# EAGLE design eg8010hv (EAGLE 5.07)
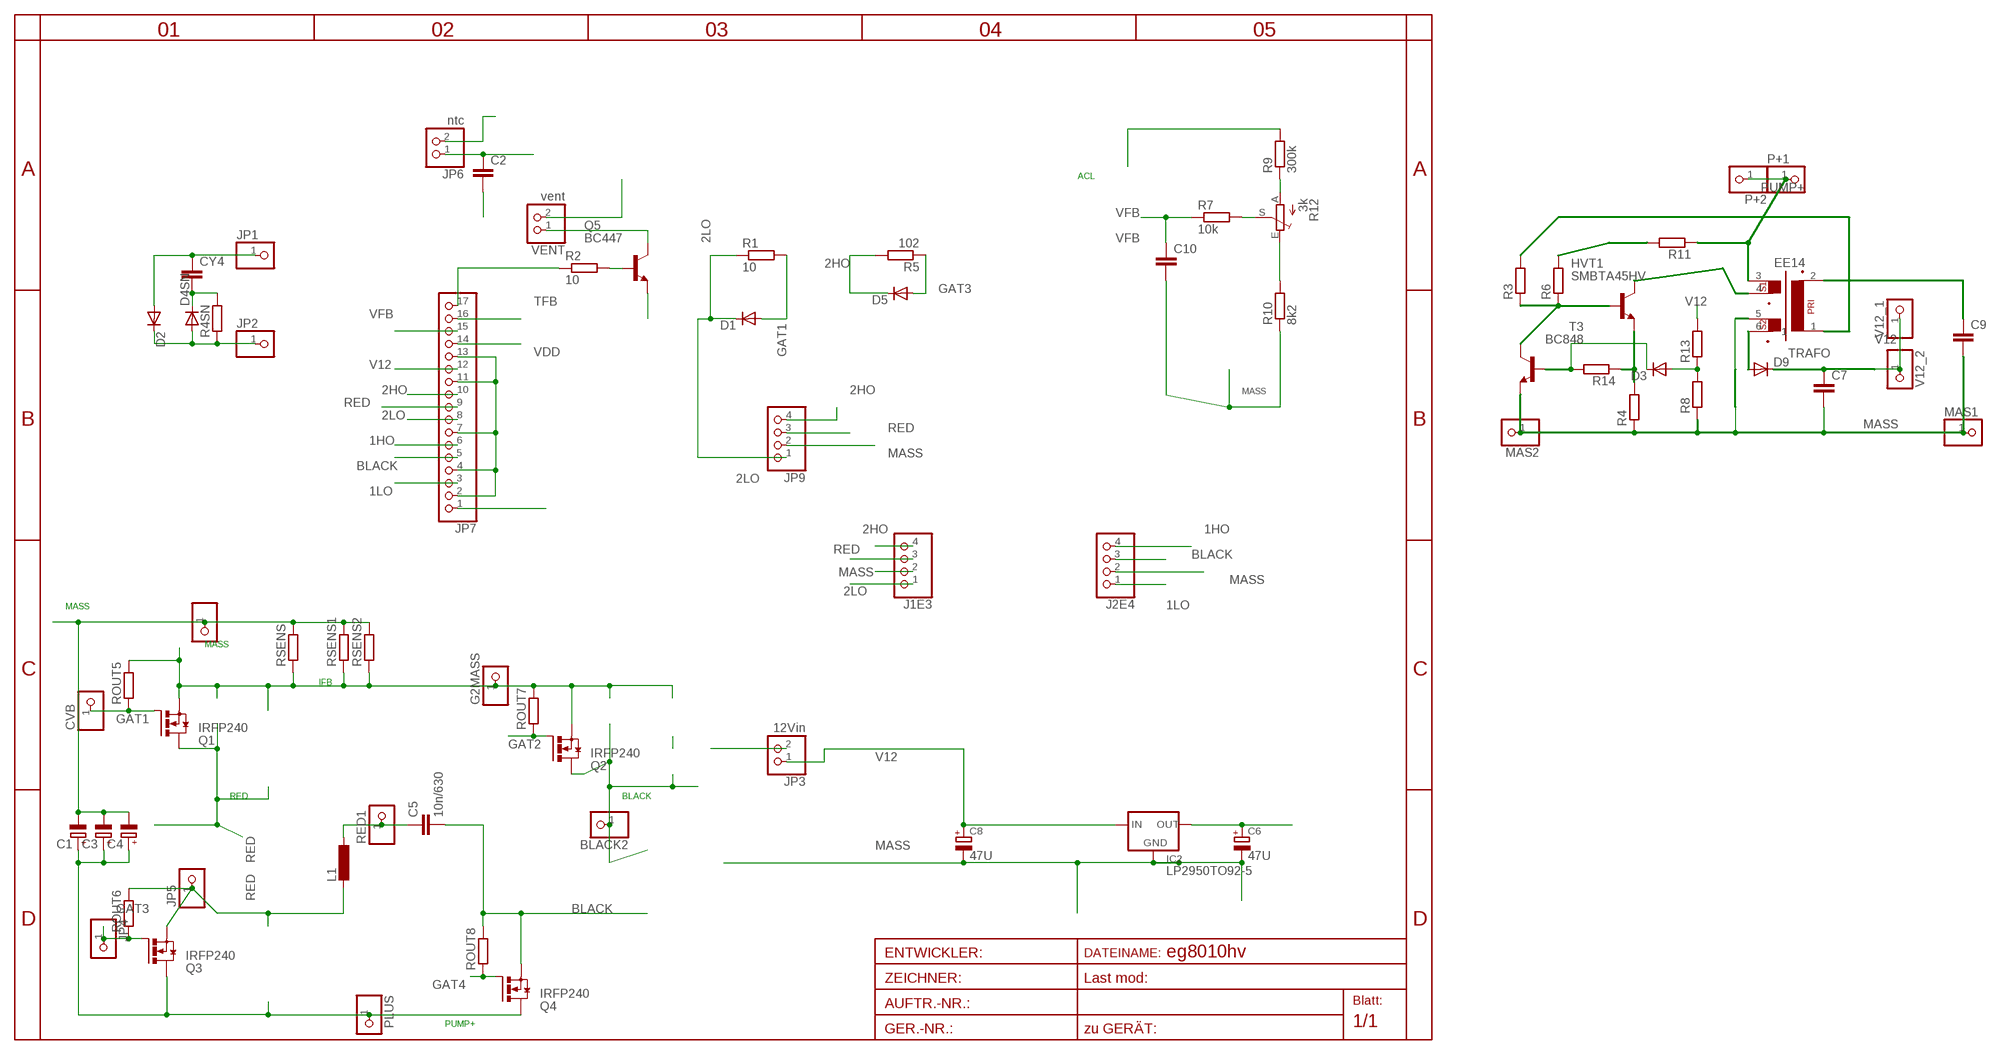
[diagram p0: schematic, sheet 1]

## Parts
BLACK2  PINHD-1X12MM3  [1X2MM3]
C1  CPOL-EUE5-13  [E5-13]
C2  C-EUC1206  [C1206]
C3  CPOL-EUE5-13  [E5-13]
C4  CPOL-EUE5-13  [E5-13]
C5  10n/630  C-EU275-173X316  [C275-173X316]
C6  47U  CPOL-EUE2.5-6  [E2,5-6]
C7  C-EUC1206  [C1206]
C8  47U  CPOL-EUE2.5-6  [E2,5-6]
C9  C-EUC0805  [C0805]
C10  C-EUC0805  [C0805]
CVB  PINHD-1X11MM0  [1X1MM0]
CY4  CXXC10B5  [XC10B5]
D1  DIODE-MINIMELF  [MINIMELF]
D2  DIODE-SMC  [SMC]
D3  DIODE-MINIMELF  [MINIMELF]
D4SN  DIODE-P1-10  [P1-10]
D5  DIODE-MINIMELF  [MINIMELF]
D9  DIODE-SMA-DO214  [SMA-DO214AC]
G2MASS  PINHD-1X11MM0  [1X1MM0]
HVT1  SMBTA45HV  [SOT23HV]
IC2  LP2950TO92-5  [T092-5]
J1E3  PINHD-1X4  [1X04]
J2E4  PINHD-1X4  [1X04]
JP1  PINHD-1X11MM0  [1X1MM0]
JP2  PINHD-1X11MM0  [1X1MM0]
JP3  12Vin  PINHD-1X2STR  [1X02]
JP4  PINHD-1X11MM0  [1X1MM0]
JP5  PINHD-1X11MM0  [1X1MM0]
JP6  ntc  PINHD-1X2STR  [1X02]
JP7  PINHD-1X17  [1X17]
JP9  PINHD-1X4  [1X04]
L1  L-EU4.13  [0204/13]
MAS1  PINHD-1X11X0.4  [1X01]
MAS2  PINHD-1X11X0.4  [1X01]
MINUS  PINHD-1X12MM3  [1X2MM3]
P+1  PINHD-1X11X0.4  [1X01]
P+2  PINHD-1X11X0.4  [1X01]
PLUS  PINHD-1X12MM3  [1X2MM3]
Q1  IRFP240  [TO247BV]
Q2  IRFP240  [TO247BV]
Q3  IRFP240  [TO247BV]
Q4  IRFP240  [TO247BV]
Q5  BC447  [TO92-EBC]
R1  10  R-EU_R0805  [R0805]
R2  10  R-EU_R0805  [R0805]
R3  R-EU_R0805  [R0805]
R4  R-EU_R0805  [R0805]
R4SN  R-EU_0207/10  [0207/10]
R5  102  R-EU_R1206  [R1206]
R6  R-EU_R1206  [R1206]
R7  10k  R-EU_R0805  [R0805]
R8  R-EU_R0805  [R0805]
R9  300k  R-EU_0207/20  [0207/20]
R10  8k2  R-EU_R0805  [R0805]
R11  R-EU_R1206  [R1206]
R12  3k  TRIM_EU-CA6V  [CA6V]
R13  R-EU_R0805  [R0805]
R14  R-EU_R0805  [R0805]
RED1  PINHD-1X12MM3  [1X2MM3]
ROUT5  R-EU_0207/10  [0207/10]
ROUT6  R-EU_0207/10  [0207/10]
ROUT7  R-EU_0207/10  [0207/10]
ROUT8  R-EU_0207/10  [0207/10]
RSENS  R-EU_0204/7  [0204/7]
RSENS1  R-EU_0204/7  [0204/7]
RSENS2  R-EU_0922V  [0922V]
T3  BC848  [SOT23]
TRAFO  EE14  [EE14]
V12_1  PINHD-1X11X0.4  [1X01]
V12_2  PINHD-1X11X0.4  [1X01]
VENT  vent  PINHD-1X2STR  [1X02]

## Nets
1HO: J2E4.4 JP7.6
1LO: J2E4.1 JP7.3
2HO: D5.C J1E3.4 JP7.10 JP9.4 R5.2
2LO: D1.C J1E3.1 JP7.8 JP9.1 R1.1
A: D9.A TRAFO.6
ACL: C5.1 L1.1 R9.2 RED1.1
B1C2: HVT1.1(B) R3.1 R6.1 T3.C
BLACK: BLACK2.1 C5.2 J2E4.3 JP7.5 Q2.D Q4.S ROUT8.2
BT1: D3.C R14.2 T3.B
C1: HVT1.3(C) TRAFO.4
DRAIN: D2.C D4SN.A JP2.1 R4SN.1
EB: HVT1.2(E) R4.2 R14.1
GAT1: CVB.1 D1.A Q1.G R1.2 ROUT5.1
GAT2: Q2.G ROUT7.1
GAT3: D5.A JP4.1 Q3.G R5.1 ROUT6.1
GAT4: Q4.G ROUT8.1
IFB: G2MASS.1 JP7.1 Q1.S Q2.S ROUT5.2 ROUT7.2 RSENS1.1 RSENS2.1 RSENS.1
MASS: C1.- C2.2 C3.- C4.- C6.- C7.2 C8.- C9.2 C10.2 IC2.2(GND) J1E3.2 J2E4.2 JP3.2 JP7.2 JP7.4 JP7.7 JP7.11 JP7.13 JP9.2 MAS1.1 MAS2.1 MINUS.1 Q5.E R4.1 R8.1 R10.1 RSENS1.2 RSENS2.2 RSENS.2 T3.E TRAFO.5
N$1: Q5.C VENT.1
N$2: Q5.B R2.2
N$3: JP7.17 R2.1
N$6: R3.2 TRAFO.1
N$7: C9.1 TRAFO.2
N$8: R6.2 R11.2
N$10: D3.A R8.2 R13.1
N$29: R10.2 R12.E
N$30: R9.1 R12.A
N$31: R7.2 R12.S
PUMP+: C1.+ C3.+ C4.+ P+1.1 P+2.1 PLUS.1 Q3.D Q4.D R11.1 TRAFO.3
RED: J1E3.3 JP5.1 JP7.9 JP9.3 L1.2 Q1.D Q3.S ROUT6.2
SNUB2: CY4.2 D4SN.C R4SN.2
SOURCE: CY4.1 D2.A JP1.1
TFB: C2.1 JP6.1 JP7.16
V12: C7.1 C8.+ D9.K(C) IC2.3(IN) JP3.1 JP7.12 R13.2 V12_1.1 V12_2.1
VDD: C6.+ IC2.1(OUT) JP6.2 JP7.14 VENT.2
VFB: C10.1 JP7.15 R7.1

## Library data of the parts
BLACK2 CVB G2MASS JP1 JP2 JP4 JP5 MAS1 MAS2 MINUS P+1 P+2 PLUS RED1 V12_1 V12_2 = pinhead:PINHD-1X1: PIN HEADER
C1 C3 C4 = rcl:CPOL-EU: POLARIZED CAPACITOR, European symbol
C2 C5 C7 C9 C10 = rcl:C-EU: CAPACITOR, European symbol
C6 C8 = rcl-2:CPOL-EU: POLARIZED CAPACITOR, European symbol
CY4 = rcl:CX: X CAPACITOR
D1-D3 D4SN D5 D9 = diode:DIODE-: DIODE
HVT1 = transistor-npn:SMBTA45
IC2 = v-reg:LP2950?*: Source: http://cache.national.com/ds/LP/LP2950.pdf
J1E3 J2E4 JP9 = pinhead:PINHD-1X4: PIN HEADER
JP3 JP6 VENT = pinhead:PINHD-1X2: PIN HEADER
JP7 = pinhead:PINHD-1X17: PIN HEADER
L1 = rcl:L-EU: INDUCTOR, European symbol
Q1-Q4 = transistor-power:IRFP240: HEXFET Power MosFet Source: http://www.irf.com/
Q5 = transistor-npn:BC447*: NPN Transistor
R1-R4 R4SN R5 R6 R8 R11 R13 R14 ROUT5-ROUT8 RSENS RSENS1 RSENS2 = rcl:R-EU_: RESISTOR, European symbol
R7 R9 R10 = rcl-2:R-EU_: RESISTOR, European symbol
R12 = pot:TRIM_EU-: POTENTIOMETER
T3 = transistor:BC848: NPN TRANSISTOR
TRAFO = trafo:EE14

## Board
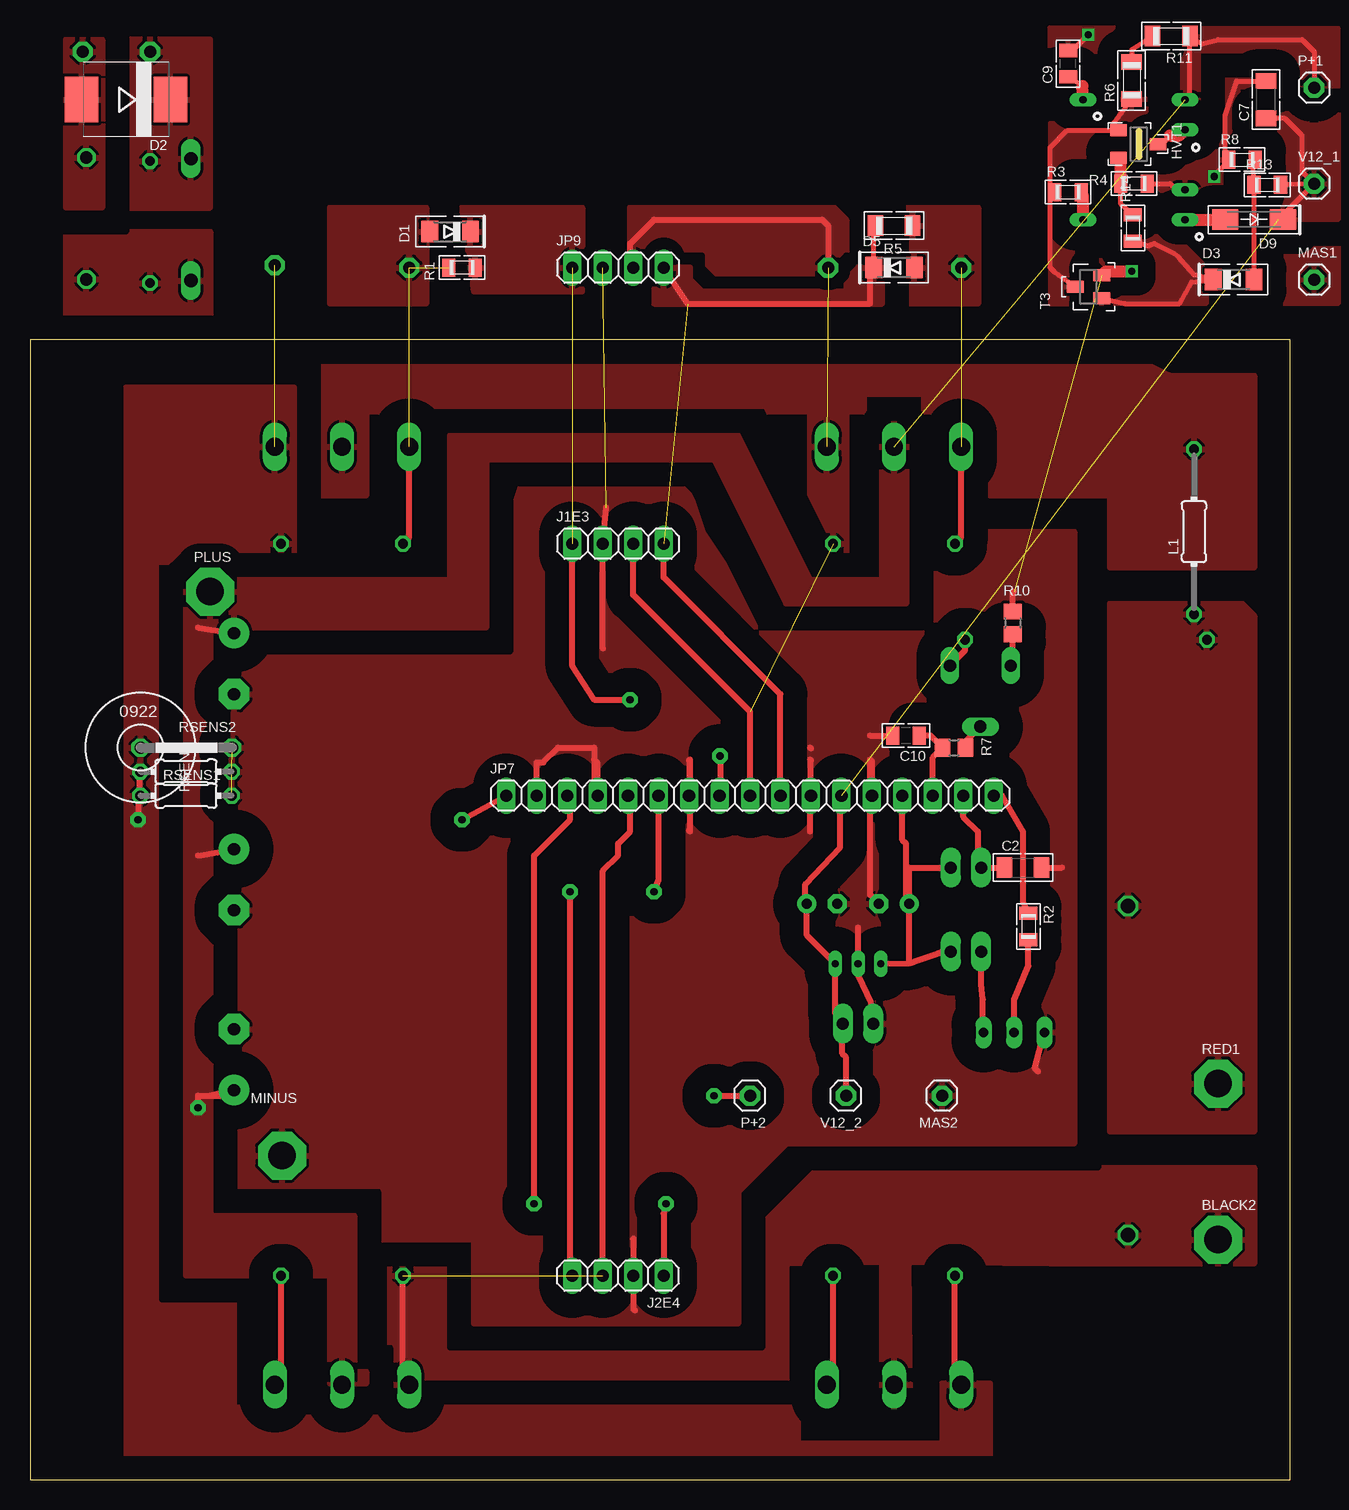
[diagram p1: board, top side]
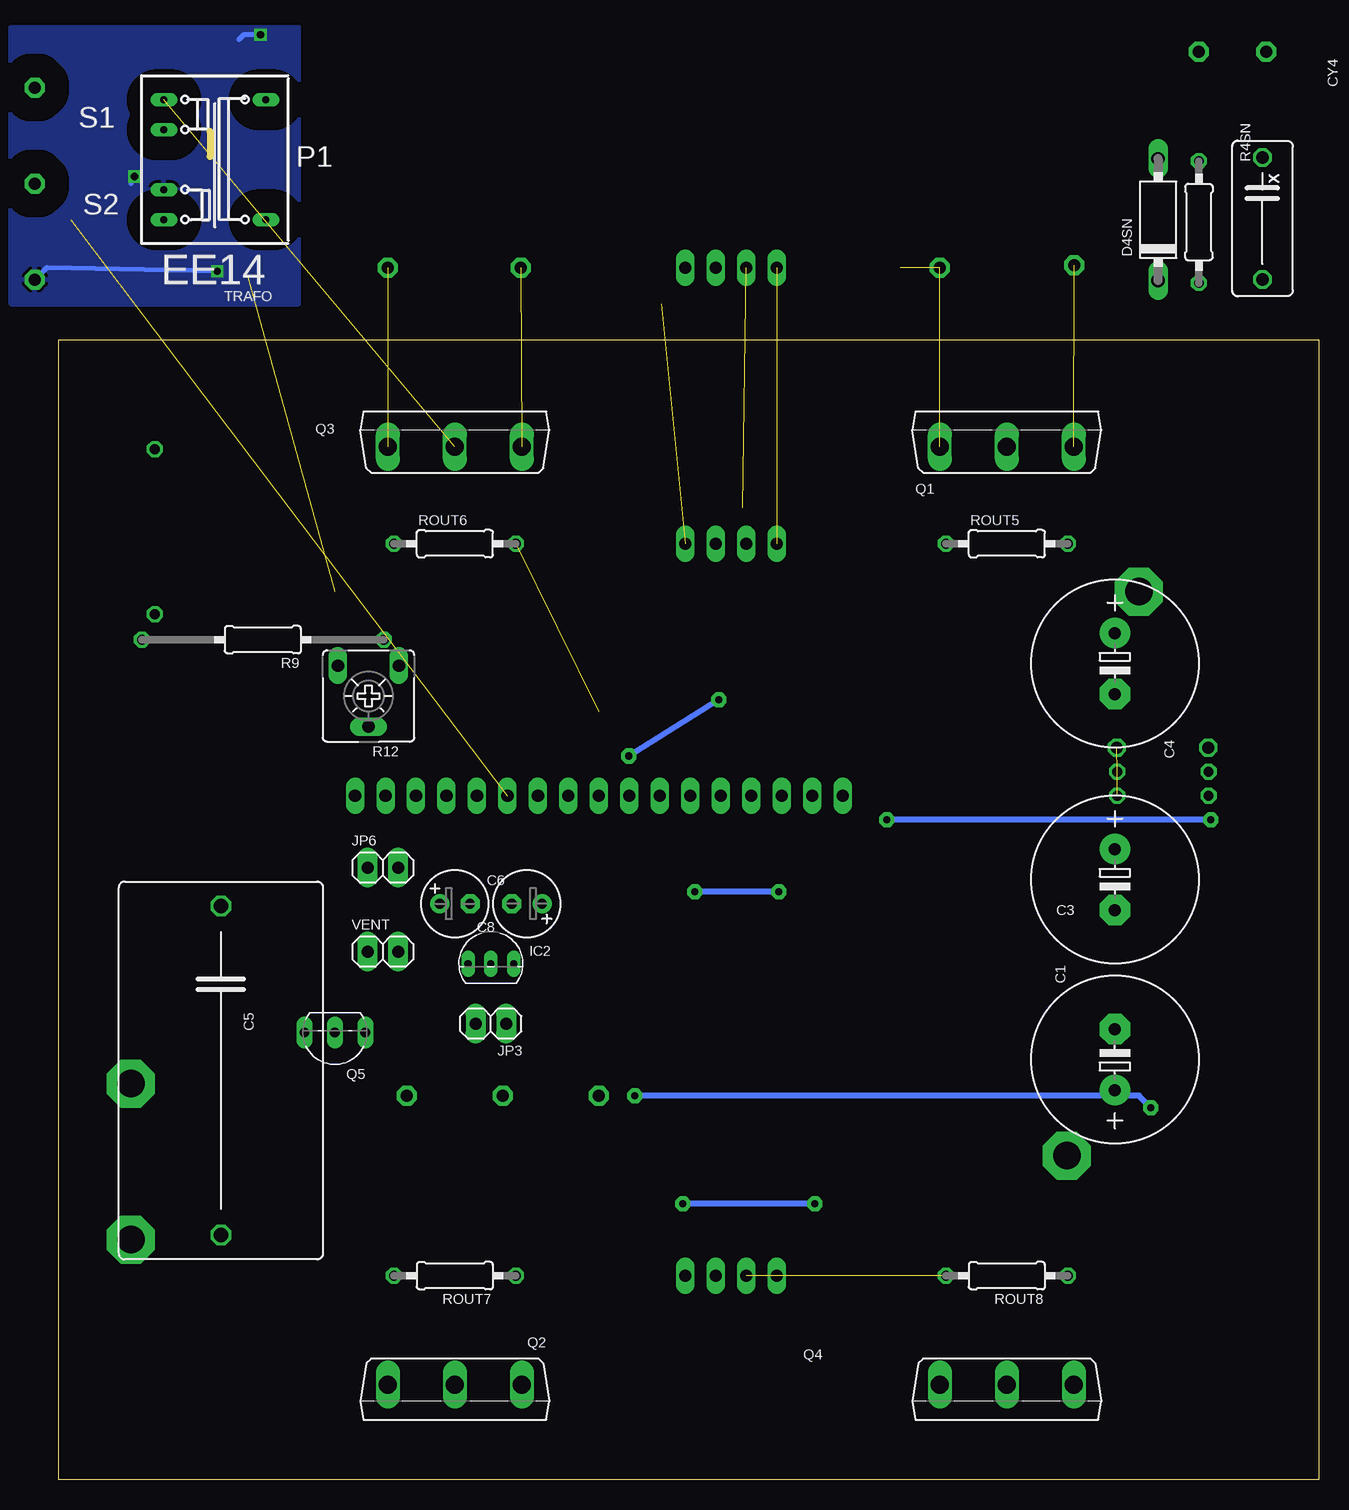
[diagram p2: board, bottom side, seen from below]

Size 105 x 95 mm. Coordinates in mm from the lower left corner, seen from the top.
Outline: 0,0 105,0 105,95 0,95 0,0
Copper layers (1*16): Top 0.035mm / dielectric 1.5mm / Bottom 0.035mm
Design rules "default *": minimum track width 10mil, minimum drill 20mil, track to track 8mil, track to pad 8mil, pad to pad 8mil, via to via 8mil, smd to smd 8mil, copper to edge 40mil, drill to drill 8mil, minimum pad ring 10mil, minimum via ring 8mil, stop-mask expansion 4mil, vias tented up to drill 0mil, thermal gap 10mil

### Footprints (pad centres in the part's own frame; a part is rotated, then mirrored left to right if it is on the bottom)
1X2MM3 = drill 2.3 pad 4 octagon: 1 0,0
E5-13 = drill 1.016 pad 2.54 round: + -2.54,0 | drill 1.016 pad 2.54 octagon: - 2.54,0
C1206 = smd 1.3 x 1.7: 1 -1.55,0; 2 1.55,0
C275-173X316 = drill 1.194 octagon: 1 -13.716,0; 2 13.716,0
E2,5-6 = drill 0.813 pad 1.6 round: + -1.27,0 | drill 0.813 pad 1.6 octagon: - 1.27,0
C0805 = smd 1.1 x 1.5: 1 -1.1,0; 2 1.1,0
1X1MM0 = drill 1 pad 1.676 octagon: 1 0,0
XC10B5 = drill 1.016 octagon: 1 -5.08,0; 2 5.08,0
MINIMELF = smd 1.4 x 1.8: A 1.7,0; C -1.7,0
SMC = smd 2.8 x 3.8: A 3.7,0; C -3.7,0
P1-10 = drill 1.118 long: A 5.08,0; C -5.08,0
SMA-DO214AC = smd 2.2 x 1.7: A 2.4,0; K -2.4,0
SOT23HV = smd 1 x 1.4: 1 -1.15,-1.7; 2 1.15,-1.7; 3 0,1.6
T092-5 = drill 0.6 pad 0.813 long: 1 -1.905,0; 2 0,0; 3 1.905,0
1X04 = drill 1.016 long: 1 -3.81,0; 2 -1.27,0; 3 1.27,0; 4 3.81,0
1X02 = drill 1.016 pad 1.676 long: 1 -1.27,0; 2 1.27,0
1X17 = drill 1.016 long: 1 -20.32,0; 2 -17.78,0; 3 -15.24,0; 4 -12.7,0; 5 -10.16,0; 6 -7.62,0; 7 -5.08,0; 8 -2.54,0; 9 0,0; 10 2.54,0; 11 5.08,0; 12 7.62,0; 13 10.16,0; 14 12.7,0; 15 15.24,0; 16 17.78,0; 17 20.32,0
0204/13 = drill 0.813 octagon: 1 -6.872,0; 2 6.872,0
1X01 = drill 1 pad 1.676 octagon: 1 0,0
TO247BV = drill 1.499 long: D 0,-2.921; G -5.588,-2.921; S 5.588,-2.921
TO92-EBC = drill 0.813 long: B 0,-1.27; C -2.54,-1.27; E 2.54,-1.27
R0805 = smd 1.1 x 1.5: 1 -1.1,0; 2 1.1,0
0207/10 = drill 0.813 octagon: 1 -5.08,0; 2 5.08,0
R1206 = smd 1.3 x 1.7: 1 -1.55,0; 2 1.55,0
R0805' = smd 1.3 x 1.5: 1 -0.95,0; 2 0.95,0
0207/20 = drill 0.813 octagon: 1 -10.08,0; 2 10.08,0
CA6V = drill 1.016 long: A -2.54,-2.54; E 2.54,-2.54; S 0,2.54
0204/7 = drill 0.813 octagon: 1 -3.81,0; 2 3.81,0
0922V = drill 1.016 octagon: 1 -5.08,0; 2 2.54,0
SOT23 = smd 1 x 1.4: B -0.95,-1.1; C 0,1.1; E 0.95,-1.1
EE14 = drill 0.6 pad 1 long: 1 4.25,-5; 2 4.25,5; 3 -4.25,5 | drill 0.6 pad 1.016 long: 4 -4.25,2.5; 5 -4.25,-2.5; 6 -4.25,-5

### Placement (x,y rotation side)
BLACK2  99,20 0 top
C1  17,35 90 bottom
C2  82.75,51 0 top
C3  17,50 270 bottom
C4  17,68 270 bottom
C5  91.5,34.1 270 bottom
C6  72,48 0 bottom
C7  103,115 90 top  (outside the outline)
C8  66,48 180 bottom
C9  86.5,118 90 top  (outside the outline)
C10  73,62 180 top
CVB  not placed on the board
CY4  not placed on the board
D1  not placed on the board
D2  not placed on the board
D3  100.3,100 0 top  (outside the outline)
D4SN  not placed on the board
D5  72,101 0 top  (outside the outline)
D9  102,105 180 top  (outside the outline)
G2MASS  not placed on the board
HVT1  92.4,111.3 270 top  (outside the outline)
IC2  69,43 0 bottom
J1E3  49,78 0 top
J2E4  49,17 180 top
JP1  not placed on the board
JP2  not placed on the board
JP3  69,38 180 bottom
JP4  not placed on the board
JP5  66.5,101 180 top  (outside the outline)
JP6  78,51 0 bottom
JP7  60,57 0 top
JP9  49,101 0 top  (outside the outline)
L1  97,79 90 top
MAS1  107,100 0 top  (outside the outline)
MAS2  76,32 180 top
MINUS  21,27 0 top
P+1  107,116 0 top  (outside the outline)
P+2  60,32 180 top
PLUS  15,74 0 top
Q1  26,89 0 bottom
Q2  72,5 180 bottom
Q3  72,89 0 bottom
Q4  26,5 180 bottom
Q5  82,36 180 bottom
R1  not placed on the board
R2  83.2,46.1 270 top
R3  86.5,107.3 0 top  (outside the outline)
R4  92,108 180 top  (outside the outline)
R4SN  not placed on the board
R5  72,104.5 180 top  (outside the outline)
R6  91.8,116.6 90 top  (outside the outline)
R7  10k  [R0805']  77,61 0 top
R8  101,110 0 top  (outside the outline)
R9  88,70 180 bottom
R10  8k2  [R0805']  81.9,71.4 270 top
R11  95.1,120.3 180 top  (outside the outline)
R12  79.2,65.3 180 bottom
R13  103.1,107.9 0 top  (outside the outline)
R14  91.9,104.3 270 top  (outside the outline)
RED1  99,33 0 top
ROUT5  26,78 0 bottom
ROUT6  72,78 0 bottom
ROUT7  72,17 180 bottom
ROUT8  26,17 180 bottom
RSENS  13,59 0 top
RSENS1  13,57 0 top
RSENS2  14.3,61 0 top
T3  88.2,99.4 90 top  (outside the outline)
TRAFO  92,110 0 bottom  (outside the outline)
V12_1  107,108 0 top  (outside the outline)
V12_2  68,32 180 top
VENT  78,44 0 bottom

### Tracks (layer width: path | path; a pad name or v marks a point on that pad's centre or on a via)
1HO  (via drill 0.6 pad 1.27)
  Top 0.5: J2E4.4 45,17 v45,49 | v52,49 52.38,50 JP7.6
  Bottom 0.5: v45,49 v52,49
1LO  (via drill 0.6 pad 1.27)
  Top 0.5: J2E4.1 52.81,22.19 v53,23 | v42,23 42,52 45,55 45,56.76 JP7.3
  Bottom 0.5: v42,23 v53,23
2HO  (1 unrouted)
  Top 0.406: R5.2 70.3,104.5 D5.C
  Top 0.5: D5.C 70,101 70,98 54.81,98 JP9.4 | JP7.10 62.54,65.46 52.81,75.19 J1E3.4
  pour Top (isolate 1): 52,101 52,98 71,98 71,101 69,101 68,100 68,99 56,99 55,100 55,101
2LO  (via drill 0.6 pad 1.27)  (1 unrouted)
  Top 0.5: J1E3.1 45.19,67.81 47,65 v50,65 | v57.4,57 57.5,57 v57.5,60.3
  Bottom 0.5: v57.4,57 JP7.8 | v50,65 v57.5,60.3
  pour Top (isolate 1): 36,106 46,106 46,99 37,99
A
  Top 1: TRAFO.6 D9.A
ACL
  pour Top (isolate 1): 90,73 101,73 102,72 102,29 90,29
B1C2
  Top 0.406: R6.1 90.3,113.05 HVT1.1 86.45,112.45 85,111 85,107.9 | 85,107.7 R3.1 85,107.9 | T3.C 85.4,100.6 85,101 85,107.7 | 85,107.7 85,107.9
  pour Top (isolate 2): 90,113 85,113 85,98 88,98 88,111 90,111 93,114 93,116 91,116
BLACK  (1 unrouted)
  Top 0.5: ROUT8.2 31.08,8.43 Q4.S | J2E4.3 47.73,50.73 49,52 49,53 50,54 50,56.84 JP7.5
  pour Top (isolate 2, rank 4): 30,18 35,18 35,11 61,11 61,22 65,26 102,26 102,18 85,18 73.2,18.1 73.3,6.1 71,6.1 71,18.1 63,18 63,8 30,7
BT1
  Top 0.406: T3.B 91.25,98 95.8,98 96.8,99.8 D3.C 97,100.4 95.7,101.9 95.3,102.2 93.7,103 93.2,102.8 R14.2
  pour Top (isolate 1.5, rank 2): 92,105 94,105 98,101 98,98 89,98 89,100 90,100 92,102
C1
  Top 0.406: HVT1.3 94.3,111.3 95,112
  Top 1: 95,112 95.75,112 TRAFO.4
DRAIN
  pour Top (isolate 2, rank 2): 8,120 8,106 15,106 15,120
EB
  Top 0.406: R14.1 90.9,106.3 R4.2 | 90.9,109.95 HVT1.2
  Top 1: R4.2 90.9,109.95
GAT1  (2 unrouted)
  Top 0.5: Q1.G 31.59,78.51 ROUT5.1
  pour Top (isolate 2): 25,98 25,106 33,106 33,98
GAT2
  Top 0.5: ROUT7.1 66.92,8.43 Q2.G
GAT3  (1 unrouted)
  Top 0.5: Q3.G 77.59,78.51 ROUT6.1
  pour Top (isolate 2, rank 2): 73,106 79,106 79,98 73,98
GAT4
  Top 0.5: ROUT8.1 20.92,8.43 Q4.G
IFB  (via drill 0.6 pad 1.27)  (1 unrouted)
  Top 0.5: v36,55 JP7.1 | v9,55 RSENS.1 | ROUT7.2 77.08,8.92 78,8 78,7.51 | 78,7.51 78,7 | Q2.S 78,7.51
  Bottom 0.5: v9,55 v36,55
  pour Top (isolate 2, rank 3): 22,91 8,91 8,2 12,0 80,0 80,8 76,8 76,3 64,3 64,6 17,6 17,17 11,17 11,69 22,69
MASS  (via drill 0.6)  (4 unrouted)
  Top 0.406: C7.2 100.55,116.55 99.6,113.7 99.6,110.8 R8.1 99.9,109.9 v98.7,108.6 | C9.2 86.9,119.1 v88.2,120.4 | TRAFO.5 95.5,107.5 95,108 R4.1
  Top 0.5: 47.73,69.27 J1E3.2 48,81 | 55,54 54.92,54.08 55,54.16 55,60 54.92,59.92 JP7.7 | 47,60 47.3,59.7 JP7.4 47,57.3 47,61 44,61 42.78,59.78 42.22,59.78 JP7.2 | 65.08,60.92 65,61 | 69,42 70.1,39.7 70.1,39.43 JP3.2 | R10.1 81.9,73.9 82,74 | Q5.E 83.73,34.27 84,34 | JP7.13 70.16,59.84 70,60 70,48.73 C6.- | JP7.11 65.08,59.92 65,60 | C2.2 86,51 | 70,62 C10.2 | 65,54 65,57 | J2E4.2 50.27,20.07 50.3,20.1 50.3,14.2 50.4,14.1 | IC2.2 69,46
  Top 1: v91.8,100.7 89.65,100.7 T3.E
  Bottom 0.406: v91.8,100.7 106,101 MAS1.1 | v88.2,120.4 89.6,120.4 90,120 | v98.7,108.6 99,108
  pour Top (isolate 2, rank 3): 16,20 16,70 39,71 39,77 41,83 54,83 55,82 56,79 60,73 73,73 73,79 87,79 87,28 63,28 59,24 59,13 37,13 37,20
  pour Bottom (isolate 2): 85,121 109,121 109,98 85,98 85,99
  pour Top (isolate 2, rank 5): 85,121 109,121 109,98 85,98 85,99
N$1
  Top 0.5: VENT.1 79.27,41.27 79.4,40 79.4,36.81 Q5.C
N$2
  Top 0.5: R2.2 83.2,42.8 82,40 Q5.B
N$3
  Top 0.5: JP7.17 81,57 82.75,54 82.75,48.1 R2.1
N$6
  Top 0.406: 87.75,106.95 R3.2
  Top 1: TRAFO.1 87.75,106.95
N$7
  Top 0.406: 87.7,116.15 C9.1
  Top 1: TRAFO.2 87.7,116.15
N$8
  Top 0.406: R11.2 91.85,119.2 R6.2
N$10
  Top 0.406: R8.2 101.9,109.8 R13.1 D3.A
N$29
  Top 0.5: R10.2 81.9,68 R12.E
N$30
  Top 0.5: R9.1 77.92,69.1 R12.A
N$31
  Top 0.5: R7.2 77.95,61.51 R12.S
PUMP+  (via drill 0.6 pad 1.27)  (1 unrouted)
  Top 0.406: P+1.1 107,119 106,120 99,120 97.65,119.65 R11.1 96.65,115.4 TRAFO.3
  Top 0.5: 16.17,32.27 15,32 | 16.17,32.27 C1.+ | 14,52 C3.+ | 14,71 C4.+ | v57,32 P+2.1 | v14,31 14,32 15.9,32 16.17,32.27
  Bottom 0.5: v57,32 15,32 v14,31
  pour Top (isolate 2): 13,75 35,75 35,87 59,87 65,75 71,75 71,88 73,88 73,73 63,73 57,85 38,85 38,71 15,71 15,22 27,22 27,9 28,9 28,8 25,8 25,17 13,17
  pour Top (isolate 2, rank 2): 96,121 109,121 109,116 105,116 105,119 97.4,119 97.4,115 96,115
RED  (2 unrouted)
  Top 0.5: JP5.1 66.5,104.5 66,105 52,105 50,103 50,101.27 JP9.3 | JP7.9 60,64 50.27,73.73 J1E3.3
  pour Top (isolate 2, rank 4): 28,82 24,82 24,93 93,93 95,92 102,92 102,76 90,76 90,82 80,82 80,89 68,89 68,77 65,77 65,89 28,89
  pour Top (isolate 1, rank 2): 50,102 50,105 50,106 67,106 68,105 68,101 67,100 57,100 54,103 53,103 52,102 52,101
SNUB2
  pour Top (isolate 2, rank 2): 3,104 15,104 15,97 3,97
SOURCE
  pour Top (isolate 2): 3,120 6,120 6,106 3,106
TFB
  Top 0.5: JP7.16 77.78,55.22 79,54 79,51.27 JP6.1 C2.1
V12  (1 unrouted)
  Top 0.406: C7.1 104.55,113.45 106,112 106,109 V12_1.1 | V12_1.1 R13.2 | D9.K 104,105 V12_1.1
  Top 0.5: JP7.12 67.5,56.32 67.5,52.7 64.62,49.62 64.62,48.11 C8.+ 64.73,45.37 IC2.3 67.09,38.91 68,38 JP3.1 67.7,37.97 67.7,35.5 68,35.2 V12_2.1
  pour Top (isolate 2): 103,114 109,114 109,113 109,105 104,105 104,112
VDD
  Top 0.5: C6.+ 73,48.27 73,53 72.7,53.3 JP7.14 | C6.+ 73.27,44.47 73.25,43.05 | IC2.1 73.25,43.05 | JP6.2 73.27,51 C6.+ | VENT.2 76,44 73.25,43.05
VFB
  Top 0.5: C10.1 75.05,62 R7.1 75.24,60.19 JP7.15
